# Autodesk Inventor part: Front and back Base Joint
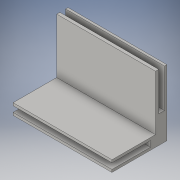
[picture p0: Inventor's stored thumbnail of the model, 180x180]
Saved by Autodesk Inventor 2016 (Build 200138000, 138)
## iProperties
Created: 2015-10
Part Number: Front and back Base Joint
Material: Generic
Document SubType Name: Modeling
Designer: ChombaW
Density: 1 g/cm^3
Appearance: Default
Author: ChombaW
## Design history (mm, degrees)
sketch "Sketch1"
  geometry: L1 (22.86, 2.54)-(-22.86, 2.54); L2 (-22.86, 2.54)-(-22.86, -2.54); L3 (-22.86, -2.54)-(22.86, -2.54); L4 (22.86, -2.54)-(22.86, 2.54); L5 (22.86, 2.54)-(-22.86, -2.54); L6 (-22.86, 2.54)-(22.86, -2.54); 1 further point
  constraints: 12 end point, 2 midpoint, 2 parallel, 1 horizontal, 1 perpendicular
  dimensions: "d0" = 45.72 distance of L3.end L2.end; "d1" = 5.08 distance of L2.end L1.end
extrude "Extrusion1" new body sketch "Sketch1" distance "d2" = 25.4; taper "d3" = 0 deg
sketch "Sketch2"
  geometry: L1 (101.6, 1.333)-(-101.6, 1.333); L2 (-101.6, 1.333)-(-101.6, -1.333); L3 (-101.6, -1.333)-(101.6, -1.333); L4 (101.6, -1.333)-(101.6, 1.333); L5 (101.6, 1.333)-(-101.6, -1.333); L6 (-101.6, 1.333)-(101.6, -1.333); 1 further point
  constraints: 12 end point, 2 midpoint, 2 parallel, 1 horizontal, 1 perpendicular
  dimensions: "d4" = 203.2 distance of L3.end L2.end; "d5" = 2.667 distance of L2.end L1.end
extrude "Extrusion2" cut sketch "Sketch2" distance "d6" = 17.78; taper "d7" = 0 deg
sketch "Sketch3"
  geometry: L1 (0, 0)-(0, -25.4) reference; L2 (45.72, 0)-(0, 0); L3 (0, 0)-(0, -5.249); L4 (0, -5.249)-(45.72, -5.249); L5 (45.72, -5.249)-(45.72, 0); 1 further point
  constraints: 8 end point, 2 parallel, 1 horizontal, 1 perpendicular, 1 point on line
extrude "Extrusion3" join sketch "Sketch3" distance "d8" = 25.4; taper "d9" = 0 deg
sketch "Sketch4"
  geometry: L1 (203.2, -3.792)-(0, -3.792); L2 (0, -3.792)-(0, -1.125); L3 (0, -1.125)-(203.2, -1.125); L4 (203.2, -1.125)-(203.2, -3.792); L5 (203.2, -3.792)-(0, -1.125); L6 (0, -3.792)-(203.2, -1.125); 2 further points
  constraints: 12 end point, 2 midpoint, 2 parallel, 1 horizontal, 1 perpendicular
  dimensions: "d10" = 203.2 distance of L2.end L3.end; "d11" = 2.667 distance of L1.end L2.end
extrude "Extrusion4" cut sketch "Sketch4" distance "d12" = 17.78; taper "d13" = 0 deg
body "Solid1"
